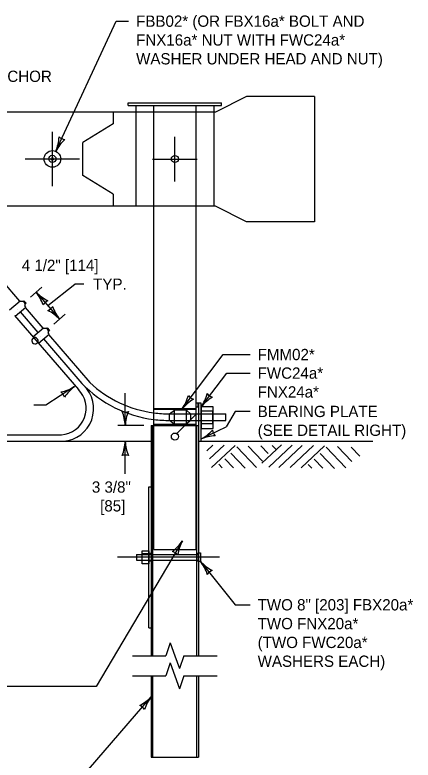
# Model space of a CAD drawing. Extents: x 49991.4 to 50021, y 49987.6 to 50011.4.
# Drawn here: x 50011.319 to 50013.434, y 49992.227 to 49996.189 of the extents above; entities that cross this region are included whole.
import ezdxf

# ---------------------------------------------------------------- set-up
doc = ezdxf.new("R2010")
doc.units = 0
for name, color, linetype in [('Level 1', 7, 'Continuous'), ('Level 2', 7, 'Continuous'), ('Level 3', 7, 'Continuous'), ('Level 4', 7, 'Continuous'), ('Level 5', 7, 'Continuous'), ('Level 6', 7, 'Continuous')]:
    doc.layers.add(name, color=color, linetype=linetype)

msp = doc.modelspace()

# ---------------------------------------------------------------- linework, layer by layer
at = {"layer": 'Level 1'}
for p, q in [((50012.5495, 49995.7555), (50012.3855, 49995.6722)), ((50012.9099, 49995.7555), (50012.5495, 49995.7555)), ((50012.9099, 49995.7555), (50012.9099, 49995.0889)), ((50011.9217, 49995.7072), (50011.9217, 49995.7222)), ((50011.9217, 49995.7222), (50012.4167, 49995.7222)), ((50012.4167, 49995.7072), (50012.4167, 49995.7222)), ((50011.9217, 49995.7072), (50012.4167, 49995.7072)), ((50011.9617, 49995.7072), (50011.9617, 49995.6722)), ((50012.0567, 49995.6722), (50012.0567, 49995.7072)), ((50012.2817, 49995.6722), (50012.2817, 49995.7072)), ((50012.3767, 49995.7072), (50012.3767, 49995.6722)), ((50012.3855, 49995.6722), (50008.9005, 49995.6722)), ((50011.8412, 49995.6722), (50011.8412, 49995.6098)), ((50012.2817, 49995.6722), (50012.0567, 49995.6722)), ((50011.8412, 49995.6098), (50011.6808, 49995.5105)), ((50011.6808, 49995.3352), (50011.6808, 49995.5105)), ((50011.8412, 49995.2358), (50011.6808, 49995.3352)), ((50011.8412, 49995.2358), (50011.8412, 49995.1722)), ((50012.3855, 49995.1722), (50008.9005, 49995.1722)), ((50012.0567, 49994.0057), (50012.0567, 49995.1722)), ((50012.2817, 49994.0057), (50012.2817, 49995.1722)), ((50012.5495, 49995.0889), (50012.3855, 49995.1722)), ((50012.9099, 49995.0889), (50012.5495, 49995.0889)), ((50011.2492, 49994.7766), (50011.344, 49994.6667)), ((50011.291, 49994.621), (50011.3474, 49994.6696)), ((50011.3474, 49994.6696), (50011.3511, 49994.665)), ((50011.3607, 49994.6651), (50011.3667, 49994.6696)), ((50011.3667, 49994.6696), (50011.3798, 49994.6558)), ((50011.3798, 49994.6558), (50011.3738, 49994.6505)), ((50011.3203, 49994.587), (50011.3767, 49994.6357)), ((50011.3314, 49994.6253), (50011.3314, 49994.6253)), ((50011.3468, 49994.6099), (50011.4416, 49994.5)), ((50011.3767, 49994.6357), (50011.3724, 49994.6402)), ((50011.3733, 49994.6328), (50011.4681, 49994.5229)), ((50011.3163, 49994.5916), (50011.6565, 49994.1977)), ((50011.4152, 49994.4771), (50011.4714, 49994.5257)), ((50011.4714, 49994.5257), (50011.4753, 49994.5212)), ((50011.4853, 49994.5212), (50011.4904, 49994.525)), ((50011.4904, 49994.525), (50011.5035, 49994.5111)), ((50011.4446, 49994.4432), (50011.5009, 49994.4919)), ((50011.5009, 49994.4919), (50011.4966, 49994.4964)), ((50011.4974, 49994.4889), (50011.7172, 49994.2339)), ((50011.5035, 49994.5111), (50011.498, 49994.5063)), ((50011.4129, 49994.467), (50011.4194, 49994.4722)), ((50011.4356, 49994.4436), (50011.4406, 49994.4477)), ((50011.4406, 49994.4477), (50011.4446, 49994.4432)), ((50011.4555, 49994.4815), (50011.4555, 49994.4815)), ((50011.4709, 49994.466), (50011.6752, 49994.2291)), ((50012.1785, 49993.9635), (50012.2817, 49994.0667)), ((50012.3717, 49994.068), (50012.4389, 49994.068)), ((50012.4389, 49994.0332), (50012.4389, 49994.068)), ((50012.3717, 49994.0332), (50012.4389, 49994.0332)), ((50012.0437, 49994.0057), (50012.0437, 49992.7822)), ((50012.0437, 49994.0057), (50012.2937, 49994.0057)), ((50012.2937, 49994.0057), (50012.2937, 49992.7822)), ((50009.6289, 49993.9572), (50011.5667, 49993.9572)), ((50009.6289, 49993.9222), (50012.0437, 49993.9222)), ((50012.3087, 49993.9226), (50013.2199, 49993.9226)), ((50012.3385, 49993.872), (50012.3701, 49993.9017)), ((50012.3523, 49993.8282), (50012.4303, 49993.9017)), ((50012.3643, 49993.7826), (50012.4883, 49993.8995)), ((50012.4979, 49993.8924), (50012.6025, 49993.7819)), ((50012.5581, 49993.8966), (50012.6337, 49993.8168)), ((50012.6253, 49993.8986), (50012.6639, 49993.8578)), ((50012.6305, 49993.8052), (50012.7353, 49993.9039)), ((50012.6685, 49993.7838), (50012.7925, 49993.9008)), ((50012.6865, 49993.8993), (50012.7045, 49993.8801)), ((50012.7209, 49993.7831), (50012.8449, 49993.9)), ((50012.7811, 49993.7831), (50012.9053, 49993.9)), ((50012.8391, 49993.7809), (50012.9633, 49993.8978)), ((50012.9727, 49993.8907), (50013.0775, 49993.7802)), ((50013.0331, 49993.895), (50013.1085, 49993.8152)), ((50013.1061, 49993.8914), (50013.1519, 49993.843)), ((50012.4663, 49993.8594), (50012.5417, 49993.7796)), ((50012.9411, 49993.8577), (50013.0167, 49993.7779)), ((50012.4347, 49993.8285), (50012.4805, 49993.7801)), ((50012.9095, 49993.8268), (50012.9553, 49993.7784)), ((50012.4025, 49993.7998), (50012.4205, 49993.7806)), ((50012.8773, 49993.7982), (50012.8955, 49993.779)), ((50012.0313, 49992.9304), (50012.0313, 49993.6804)), ((50012.0313, 49993.6804), (50012.0445, 49993.6804)), ((50011.9645, 49993.3209), (50011.9645, 49993.2909)), ((50011.9645, 49993.3209), (50011.9949, 49993.3209)), ((50011.9645, 49993.2909), (50011.9949, 49993.2909)), ((50012.0313, 49992.9304), (50012.0435, 49992.9304)), ((50012.0437, 49992.6751), (50012.0437, 49992.2432)), ((50012.2937, 49992.6751), (50012.2937, 49992.2432)), ((50012.0437, 49992.2432), (50012.2937, 49992.2432))]:
    msp.add_line(p, q, dxfattribs=at)
for points in [[(50012.2809, 49994.1255), (50012.2809, 49994.1055), (50012.2929, 49994.1055), (50012.2929, 49994.1255)], [(50012.2937, 49994.1255), (50012.2937, 49993.9226), (50012.3087, 49993.9226), (50012.3087, 49994.1255)], [(50012.3087, 49994.1053), (50012.3087, 49993.9902), (50012.3717, 49993.9902), (50012.3717, 49994.1053)], [(50012.3087, 49994.0814), (50012.3087, 49994.0161), (50012.3711, 49994.0161), (50012.3711, 49994.0814)], [(50012.0311, 49993.3394), (50012.0311, 49993.2708), (50011.9949, 49993.2708), (50011.9949, 49993.3394)], [(50012.0313, 49993.3247), (50012.0313, 49993.2877), (50011.9951, 49993.2877), (50011.9951, 49993.3247)], [(50012.3053, 49993.3285), (50012.3053, 49993.2836), (50012.2945, 49993.2836), (50012.2945, 49993.3285)]]:
    msp.add_lwpolyline(points, close=True, dxfattribs=at)
for centre, radius in [((50011.5182, 49995.4232), 0.0442), ((50011.5182, 49995.4232), 0.0192), ((50012.1691, 49995.4227), 0.0188), ((50011.5182, 49995.4232), 0.0067), ((50012.1691, 49993.9472), 0.0188)]:
    msp.add_circle(centre, radius, dxfattribs=at)
for centre, radius, start, end in [((50011.3561, 49994.6478), 0.018, 335.0989, 106.0226), ((50011.4802, 49994.5039), 0.018, 335.4447, 105.9908), ((50011.4253, 49994.4564), 0.0164, 139.4859, 308.7941), ((50011.4246, 49994.4557), 0.018, 333.1358, 108.3769), ((50011.5642, 49994.0949), 0.1732, 274.3781, 46.0649), ((50012.1353, 49994.6714), 0.6383, 223.8727, 262.9279), ((50012.1377, 49994.6837), 0.6157, 226.9327, 262.4416), ((50011.5573, 49994.0977), 0.1408, 273.8124, 45.2371)]:
    msp.add_arc(centre, radius, start, end, dxfattribs=at)
at = {"layer": 'Level 3'}
for p, q in [((50011.5368, 49995.4645), (50011.8574, 49996.1557)), ((50011.8574, 49996.1557), (50011.9231, 49996.1557)), ((50011.4021, 49994.6889), (50011.4618, 49994.7422)), ((50011.4944, 49994.6431), (50011.6371, 49994.7573)), ((50011.6848, 49994.7573), (50011.6371, 49994.7573)), ((50011.432, 49994.7155), (50011.5568, 49994.5707)), ((50011.5269, 49994.5445), (50011.5864, 49994.5971)), ((50012.2083, 49994.0949), (50012.4259, 49994.3832)), ((50012.4259, 49994.3832), (50012.5687, 49994.3832)), ((50012.3087, 49994.1053), (50012.4441, 49994.2846)), ((50012.4441, 49994.2846), (50012.5687, 49994.2846)), ((50011.6362, 49994.2133), (50011.4832, 49994.1139)), ((50011.9053, 49994.0057), (50011.9053, 49994.1777)), ((50011.4832, 49994.1139), (50011.4193, 49994.1139)), ((50012.0037, 49994.0057), (50011.8653, 49994.0057)), ((50012.3087, 49993.9343), (50012.4408, 49993.9992)), ((50011.9053, 49993.7488), (50011.9053, 49993.9222)), ((50012.2087, 49993.3925), (50011.7516, 49992.6183)), ((50012.3053, 49993.2836), (50012.4892, 49993.0528)), ((50012.4892, 49993.0528), (50012.5687, 49993.0528)), ((50011.7516, 49992.6183), (50011.2756, 49992.6183)), ((50011.7103, 49992.1778), (50012.0437, 49992.5637))]:
    msp.add_line(p, q, dxfattribs=at)
msp.add_lwpolyline([(50012.5687, 49994.0807), (50012.49, 49994.0807), (50012.4408, 49993.9992)], dxfattribs=at)
for centre, radius, start, end in [((50011.321, 49995.5525), 0.233, 337.7991, 357.0489), ((50011.7342, 49995.3622), 0.2223, 132.4278, 152.6113), ((50011.591, 49995.5806), 0.0548, 227.1106, 262.8329), ((50011.2577, 49994.5774), 0.2223, 18.222, 38.4055), ((50011.6007, 49994.8762), 0.233, 223.5933, 242.8431), ((50011.5157, 49994.6184), 0.0548, 112.9048, 148.6271), ((50011.4731, 49994.6679), 0.0548, 292.9048, 328.6271), ((50011.388, 49994.4101), 0.233, 43.5933, 62.8431), ((50011.731, 49994.7089), 0.2223, 198.222, 218.4055), ((50011.5184, 49994.4019), 0.2223, 281.8103, 301.9939), ((50011.777, 49994.0277), 0.233, 127.1816, 146.4315), ((50011.5303, 49994.1409), 0.0548, 16.4932, 52.2155), ((50012.116, 49994.2363), 0.233, 325.7848, 345.0347), ((50012.3859, 49994.2076), 0.0548, 215.0963, 250.8187), ((50012.0156, 49994.2259), 0.233, 325.7848, 345.0347), ((50012.3801, 49993.9538), 0.2223, 120.4135, 140.597), ((50012.2855, 49994.1972), 0.0548, 215.0963, 250.8187), ((50012.4805, 49993.9642), 0.2223, 120.4135, 140.597), ((50011.9053, 49994.1314), 0.0537, 252.1388, 287.8612), ((50011.6771, 49993.9944), 0.2285, 2.8273, 22.0772), ((50012.1231, 49993.9967), 0.218, 157.456, 177.6395), ((50012.2, 49994.1352), 0.2285, 298.4193, 317.6691), ((50012.4221, 49993.9886), 0.0537, 187.7308, 223.4532), ((50012.3947, 49993.734), 0.218, 93.048, 113.2315), ((50011.6832, 49993.9314), 0.2223, 337.456, 357.6395), ((50012.138, 49993.9337), 0.233, 182.8273, 202.0772), ((50011.9053, 49993.794), 0.0548, 72.1388, 107.8612), ((50012.014, 49993.5206), 0.233, 307.4256, 326.6754), ((50012.4048, 49993.2877), 0.2223, 151.8632, 172.0467), ((50012.1436, 49993.2821), 0.0548, 41.6415, 77.3639), ((50012.1285, 49993.1488), 0.2223, 17.1265, 37.31), ((50012.4771, 49993.441), 0.233, 222.4978, 241.7476), ((50012.3871, 49993.1849), 0.0548, 111.8093, 147.5316), ((50011.8784, 49992.7214), 0.2285, 297.0949, 316.3447), ((50012.2144, 49992.4281), 0.218, 141.5325, 161.716), ((50011.9615, 49992.4685), 0.0537, 31.3109, 67.0332)]:
    msp.add_arc(centre, radius, start, end, dxfattribs=at)
at = {"layer": 'Level 4'}
for p, q in [((50011.9617, 49995.6722), (50011.9617, 49995.1722)), ((50012.0567, 49995.1722), (50012.0567, 49995.6722)), ((50012.2817, 49995.1722), (50012.2817, 49995.6722)), ((50012.3767, 49995.6722), (50012.3767, 49995.1722)), ((50012.2817, 49994.0949), (50012.0567, 49994.0949)), ((50012.2817, 49994.0911), (50012.0567, 49994.0911)), ((50012.1401, 49994.0678), (50012.1667, 49994.088)), ((50012.1667, 49994.013), (50012.1667, 49994.088)), ((50012.2307, 49994.088), (50012.1667, 49994.088)), ((50012.2307, 49994.088), (50012.2537, 49994.0658)), ((50012.1401, 49994.0344), (50012.1401, 49994.0678)), ((50012.1404, 49994.068), (50012.3711, 49994.068)), ((50012.2315, 49994.013), (50012.2315, 49994.0872)), ((50012.2537, 49994.034), (50012.2537, 49994.0658)), ((50012.2817, 49994.0107), (50012.0567, 49994.0107)), ((50012.1401, 49994.0344), (50012.1667, 49994.013)), ((50012.1416, 49994.0332), (50012.3711, 49994.0332)), ((50012.2315, 49994.013), (50012.1667, 49994.013)), ((50012.2315, 49994.013), (50012.2537, 49994.034)), ((50012.0515, 49992.7822), (50012.0515, 49994.0057)), ((50012.0565, 49993.3476), (50012.0565, 49994.0057)), ((50012.2817, 49994.0072), (50012.0567, 49994.0072)), ((50012.2815, 49993.3476), (50012.2815, 49994.0057)), ((50012.2859, 49992.7822), (50012.2859, 49994.0057)), ((50012.0565, 49993.3476), (50012.2815, 49993.3476)), ((50011.9951, 49993.3209), (50012.2945, 49993.3209)), ((50012.0313, 49993.3268), (50012.0515, 49993.3268)), ((50012.2859, 49993.3268), (50012.2937, 49993.3268)), ((50011.9951, 49993.2909), (50012.2941, 49993.2909)), ((50012.0313, 49993.2862), (50012.0515, 49993.2862)), ((50012.2859, 49993.2862), (50012.2937, 49993.2862)), ((50012.0515, 49992.2432), (50012.0515, 49992.6751)), ((50012.2859, 49992.2432), (50012.2859, 49992.6751))]:
    msp.add_line(p, q, dxfattribs=at)
for centre, radius, start, end in [((50012.1377, 49994.6837), 0.6157, 262.4416, 270.2523), ((50012.1353, 49994.6714), 0.6383, 262.9279, 270.5676)]:
    msp.add_arc(centre, radius, start, end, dxfattribs=at)
at = {"layer": 'Level 5'}
for p, q in [((50011.5182, 49995.279), (50011.5182, 49995.5674)), ((50012.1691, 49995.3039), (50012.1691, 49995.5414)), ((50011.3739, 49995.4232), (50011.6623, 49995.4232)), ((50012.0504, 49995.4227), (50012.2879, 49995.4227)), ((50012.4053, 49993.3065), (50011.8645, 49993.3065))]:
    msp.add_line(p, q, dxfattribs=at)
at = {"layer": 'Level 6'}
for p, q in [((50012.1444, 49992.8508), (50012.1201, 49992.7822)), ((50012.1444, 49992.8508), (50012.1687, 49992.7822)), ((50011.9437, 49992.7822), (50012.1201, 49992.7822)), ((50012.1687, 49992.7822), (50012.193, 49992.7136)), ((50012.2173, 49992.7822), (50012.193, 49992.7136)), ((50012.2173, 49992.7822), (50012.3937, 49992.7822)), ((50012.1444, 49992.7437), (50012.1201, 49992.6751)), ((50012.1444, 49992.7437), (50012.1687, 49992.6751)), ((50011.9437, 49992.6751), (50012.1201, 49992.6751)), ((50012.1687, 49992.6751), (50012.193, 49992.6065)), ((50012.2173, 49992.6751), (50012.193, 49992.6065)), ((50012.2173, 49992.6751), (50012.3937, 49992.6751))]:
    msp.add_line(p, q, dxfattribs=at)

# ---------------------------------------------------------------- texts
at = {"layer": 'Level 2'}
for s, p in [('FBB02* (OR FBX16a* BOLT AND', (50011.9631, 49996.1257)), ('FNX16a* NUT WITH FWC24a*', (50011.9631, 49996.0257)), ('WASHER UNDER HEAD AND NUT)', (50011.9631, 49995.9257)), ('FPA01* ANCHOR', (50010.8689, 49995.8325)), ('4 1/2" [114]', (50011.3559, 49994.8273)), ('TYP.', (50011.7349, 49994.7273)), ('FMM02*', (50012.6087, 49994.3533)), ('FWC24a*', (50012.6087, 49994.2546)), ('FNX24a*', (50012.6087, 49994.1546)), ('BEARING PLATE', (50012.6087, 49994.0507)), ('(SEE DETAIL RIGHT)', (50012.6087, 49993.9507)), ('3 3/8"', (50011.7282, 49993.6488)), ('[85]', (50011.772, 49993.5488)), ('TWO 8" [203] FBX20a*', (50012.6087, 49993.0228)), ('TWO FNX20a*', (50012.6087, 49992.9228)), ('(TWO FWC20a*', (50012.6087, 49992.8228)), ('WASHERS EACH)', (50012.6087, 49992.7228))]:
    msp.add_text(s, height=0.06, dxfattribs=at).set_placement(p)

doc.saveas('drawing.dxf')
